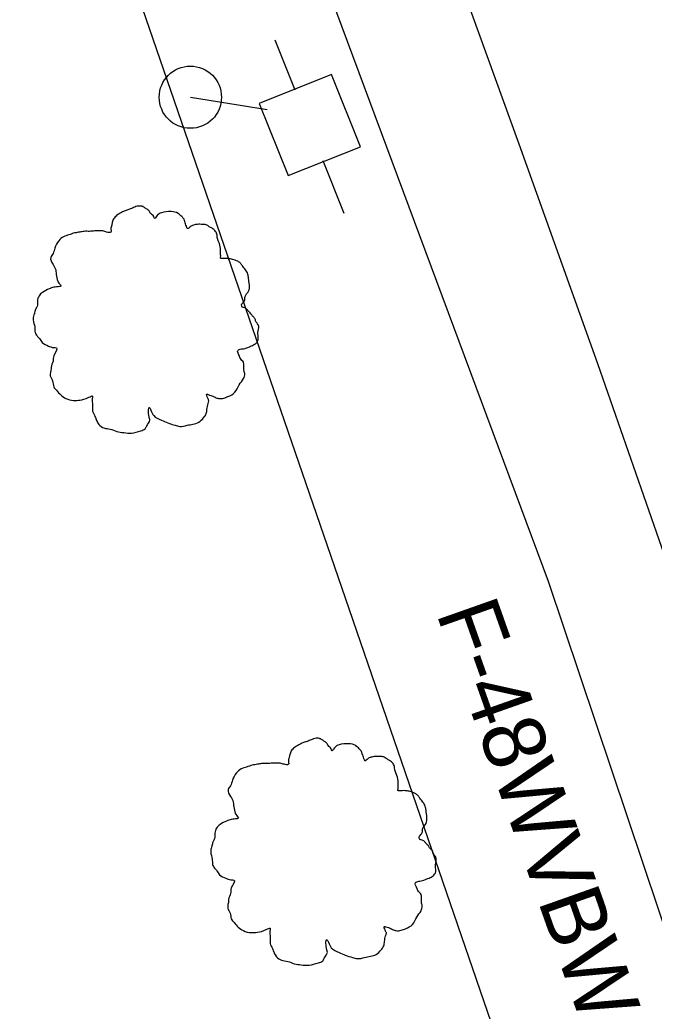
# Model space of a CAD drawing. Extents: x 2004847 to 2009016, y 1134161 to 1140101.
# Drawn here: x 2005383.6 to 2005424.3, y 1139014.6 to 1139078.3 of the extents above; entities that cross this region are included whole.
import ezdxf

# ---------------------------------------------------------------- set-up
doc = ezdxf.new("R2010")
doc.units = 0
for name, color, linetype in [('RD_EX_Fence_Other', 7, 'Continuous'), ('RD_EX_H2O', 7, 'Continuous'), ('RD_EX_Road', 7, 'Continuous'), ('RD_EX_UT', 7, 'Continuous'), ('RD_EX_VEG', 7, 'Continuous'), ('RD_Sketch3', 7, 'Continuous')]:
    doc.layers.add(name, color=color, linetype=linetype)

msp = doc.modelspace()

# ---------------------------------------------------------------- linework, layer by layer
at = {"layer": 'RD_EX_Fence_Other'}
msp.add_lwpolyline([(2005745.196, 1138077.702), (2005734.871, 1138106.228), (2005707.504, 1138183.279), (2005676.139, 1138273.059), (2005651.835, 1138341.758), (2005621.989, 1138424.972), (2005599.093, 1138488.219), (2005571.206, 1138570.22), (2005540.215, 1138656.024), (2005513.7, 1138731.214), (2005485.608, 1138810.484), (2005460.949, 1138877.537), (2005433.241, 1138957.412), (2005403.809, 1139043.224), (2005384.611, 1139099.043), (2005341.775, 1139216.012), (2005309.562, 1139306.929), (2005274.937, 1139406.133)], dxfattribs=at)
at = {"layer": 'RD_EX_H2O'}
msp.add_lwpolyline([(2005471.871, 1138887.945), (2005471.871, 1138887.945), (2005442.962, 1138966.495), (2005417.558, 1139042.223), (2005389.586, 1139117.406), (2005362.32, 1139191.545), (2005330.803, 1139259.793), (2005304.78, 1139341.828)], dxfattribs=at)
at = {"layer": 'RD_EX_Road'}
msp.add_lwpolyline([(2005335.767, 1139296.554), (2005340.823, 1139282.434), (2005345.843, 1139268.3), (2005350.89, 1139254.176), (2005355.796, 1139240.002), (2005360.862, 1139225.885), (2005365.791, 1139211.783), (2005370.883, 1139197.68), (2005375.796, 1139183.516), (2005380.897, 1139169.417), (2005385.734, 1139155.226), (2005390.637, 1139141.059), (2005395.446, 1139126.858), (2005400.445, 1139112.697), (2005405.292, 1139098.51), (2005410.544, 1139084.465), (2005415.646, 1139070.367), (2005420.7, 1139056.252), (2005425.641, 1139042.098), (2005430.526, 1139027.924), (2005435.34, 1139013.754), (2005440.253, 1138999.592), (2005445.203, 1138985.442), (2005450.39, 1138971.373)], dxfattribs=at)
at = {"layer": 'RD_EX_UT'}
for p, q in [((2005399.958, 1139077.064), (2005401.244, 1139073.842)), ((2005403.609, 1139074.827), (2005398.966, 1139072.974)), ((2005405.463, 1139070.184), (2005403.609, 1139074.827)), ((2005394.535, 1139073.368), (2005399.472, 1139072.575)), ((2005398.966, 1139072.974), (2005400.819, 1139068.33)), ((2005400.819, 1139068.33), (2005405.463, 1139070.184)), ((2005403.056, 1139069.3), (2005404.406, 1139065.919))]:
    msp.add_line(p, q, dxfattribs=at)
msp.add_circle((2005394.535, 1139073.368), 1.999, dxfattribs=at)
at = {"layer": 'RD_EX_VEG'}
for points in [[(2005391.505, 1139066.343), (2005391.205, 1139066.368), (2005390.88, 1139066.268), (2005390.631, 1139066.168), (2005390.406, 1139066.093), (2005390.181, 1139065.993), (2005389.881, 1139065.818), (2005389.656, 1139065.618), (2005389.531, 1139065.368), (2005389.481, 1139065.143), (2005389.431, 1139064.868), (2005389.431, 1139064.693), (2005389.306, 1139064.668), (2005389.156, 1139064.693), (2005388.906, 1139064.768), (2005388.656, 1139064.768), (2005388.406, 1139064.768), (2005388.057, 1139064.743), (2005387.707, 1139064.743), (2005387.432, 1139064.693), (2005387.107, 1139064.643), (2005386.732, 1139064.518), (2005386.382, 1139064.393), (2005386.083, 1139064.143), (2005385.833, 1139063.669), (2005385.708, 1139063.319), (2005385.558, 1139063.069), (2005385.708, 1139062.619), (2005385.883, 1139062.269), (2005385.908, 1139062.069), (2005385.983, 1139061.645), (2005386.083, 1139061.42), (2005386.207, 1139061.22), (2005386.133, 1139061.195), (2005385.758, 1139061.145), (2005385.458, 1139061.045), (2005385.033, 1139060.82), (2005384.808, 1139060.595), (2005384.708, 1139060.27), (2005384.683, 1139059.92), (2005384.583, 1139059.72), (2005384.508, 1139059.446), (2005384.483, 1139059.371), (2005384.433, 1139059.046), (2005384.533, 1139058.596), (2005384.558, 1139058.246), (2005384.683, 1139058.021), (2005384.833, 1139057.846), (2005385.008, 1139057.596), (2005385.408, 1139057.371), (2005385.733, 1139057.271), (2005385.933, 1139057.247), (2005385.758, 1139056.747), (2005385.708, 1139056.397), (2005385.583, 1139055.997), (2005385.583, 1139055.922), (2005385.533, 1139055.447), (2005385.683, 1139055.122), (2005385.758, 1139054.748), (2005385.933, 1139054.523), (2005386.207, 1139054.223), (2005386.532, 1139053.998), (2005387.032, 1139053.873), (2005387.432, 1139053.898), (2005388.007, 1139054.073), (2005388.257, 1139054.148), (2005388.232, 1139053.973), (2005388.257, 1139053.598), (2005388.257, 1139053.173), (2005388.406, 1139052.848), (2005388.506, 1139052.574), (2005388.656, 1139052.324), (2005388.981, 1139052.099), (2005389.381, 1139052.024), (2005389.806, 1139051.874), (2005390.256, 1139051.799), (2005390.755, 1139051.774), (2005391.355, 1139051.924), (2005391.63, 1139052.049), (2005391.73, 1139052.224), (2005391.93, 1139052.599), (2005391.88, 1139052.823), (2005391.905, 1139053.423), (2005392.005, 1139053.248), (2005392.18, 1139052.898), (2005392.68, 1139052.599), (2005393.079, 1139052.424), (2005393.554, 1139052.274), (2005393.854, 1139052.199), (2005394.329, 1139052.274), (2005394.704, 1139052.349), (2005395.079, 1139052.474), (2005395.378, 1139052.748), (2005395.553, 1139053.023), (2005395.603, 1139053.298), (2005395.678, 1139053.673), (2005395.728, 1139053.848)], [(2005391.505, 1139066.343), (2005391.205, 1139066.368), (2005390.88, 1139066.268), (2005390.631, 1139066.168), (2005390.406, 1139066.093), (2005390.181, 1139065.993), (2005389.881, 1139065.818), (2005389.656, 1139065.618), (2005389.531, 1139065.368), (2005389.481, 1139065.143), (2005389.431, 1139064.868), (2005389.431, 1139064.693), (2005389.306, 1139064.668), (2005389.156, 1139064.693), (2005388.906, 1139064.768), (2005388.656, 1139064.768), (2005388.406, 1139064.768), (2005388.057, 1139064.743), (2005387.707, 1139064.743), (2005387.432, 1139064.693), (2005387.107, 1139064.643), (2005386.732, 1139064.518), (2005386.382, 1139064.393), (2005386.083, 1139064.143), (2005385.833, 1139063.669), (2005385.708, 1139063.319), (2005385.558, 1139063.069), (2005385.708, 1139062.619), (2005385.883, 1139062.269), (2005385.908, 1139062.069), (2005385.983, 1139061.645), (2005386.083, 1139061.42), (2005386.207, 1139061.22), (2005386.133, 1139061.195), (2005385.758, 1139061.145), (2005385.458, 1139061.045), (2005385.033, 1139060.82), (2005384.808, 1139060.595), (2005384.708, 1139060.27), (2005384.683, 1139059.92), (2005384.583, 1139059.72), (2005384.508, 1139059.446), (2005384.483, 1139059.371), (2005384.433, 1139059.046), (2005384.533, 1139058.596), (2005384.558, 1139058.246), (2005384.683, 1139058.021), (2005384.833, 1139057.846), (2005385.008, 1139057.596), (2005385.408, 1139057.371), (2005385.733, 1139057.271), (2005385.933, 1139057.247), (2005385.758, 1139056.747), (2005385.708, 1139056.397), (2005385.583, 1139055.997), (2005385.583, 1139055.922), (2005385.533, 1139055.447), (2005385.683, 1139055.122), (2005385.758, 1139054.748), (2005385.933, 1139054.523), (2005386.207, 1139054.223), (2005386.532, 1139053.998), (2005387.032, 1139053.873), (2005387.432, 1139053.898), (2005388.007, 1139054.073), (2005388.257, 1139054.148), (2005388.232, 1139053.973), (2005388.257, 1139053.598), (2005388.257, 1139053.173), (2005388.406, 1139052.848), (2005388.506, 1139052.574), (2005388.656, 1139052.324), (2005388.981, 1139052.099), (2005389.381, 1139052.024), (2005389.806, 1139051.874), (2005390.256, 1139051.799), (2005390.755, 1139051.774), (2005391.355, 1139051.924), (2005391.63, 1139052.049), (2005391.73, 1139052.224), (2005391.93, 1139052.599), (2005391.88, 1139052.823), (2005391.905, 1139053.423), (2005392.005, 1139053.248), (2005392.18, 1139052.898), (2005392.68, 1139052.599), (2005393.079, 1139052.424), (2005393.554, 1139052.274), (2005393.854, 1139052.199), (2005394.329, 1139052.274), (2005394.704, 1139052.349), (2005395.079, 1139052.474), (2005395.378, 1139052.748), (2005395.553, 1139053.023), (2005395.603, 1139053.298), (2005395.678, 1139053.673), (2005395.728, 1139053.848)], [(2005395.728, 1139053.848), (2005395.653, 1139054.023), (2005395.603, 1139054.273), (2005395.678, 1139054.248), (2005395.853, 1139054.198), (2005396.128, 1139054.073), (2005396.353, 1139053.998), (2005396.678, 1139054.023), (2005396.953, 1139054.123), (2005397.403, 1139054.398), (2005397.677, 1139054.873), (2005397.952, 1139055.272), (2005398.027, 1139055.597), (2005397.977, 1139055.822), (2005397.952, 1139056.322), (2005397.752, 1139056.572), (2005397.702, 1139056.697), (2005397.602, 1139057.097), (2005397.677, 1139057.147), (2005397.952, 1139057.197), (2005398.327, 1139057.321), (2005398.602, 1139057.446), (2005398.827, 1139057.621), (2005398.902, 1139057.846), (2005398.877, 1139058.246), (2005398.927, 1139058.646), (2005398.852, 1139058.796), (2005398.752, 1139058.946), (2005398.677, 1139059.146), (2005398.527, 1139059.296), (2005398.427, 1139059.446), (2005398.327, 1139059.545), (2005398.202, 1139059.695), (2005398.027, 1139059.82), (2005397.877, 1139059.87), (2005397.827, 1139060.02), (2005397.977, 1139060.22), (2005398.027, 1139060.32), (2005398.052, 1139060.545), (2005398.277, 1139060.895), (2005398.327, 1139061.295), (2005398.277, 1139061.72), (2005398.227, 1139061.994), (2005398.077, 1139062.269), (2005397.877, 1139062.519), (2005397.752, 1139062.694), (2005397.577, 1139062.819), (2005397.253, 1139062.944), (2005397.003, 1139062.994), (2005396.653, 1139062.994), (2005396.453, 1139063.044), (2005396.478, 1139063.094), (2005396.478, 1139063.244), (2005396.478, 1139063.519), (2005396.403, 1139063.969), (2005396.253, 1139064.468), (2005396.253, 1139064.493), (2005396.153, 1139064.743), (2005395.928, 1139064.943), (2005395.753, 1139065.043), (2005395.553, 1139065.168), (2005395.303, 1139065.193), (2005395.004, 1139065.193), (2005394.729, 1139065.143), (2005394.529, 1139065.043), (2005394.354, 1139064.918), (2005394.279, 1139065.068), (2005394.179, 1139065.368), (2005394.129, 1139065.518), (2005393.979, 1139065.693), (2005393.754, 1139065.893), (2005393.304, 1139066.018), (2005392.68, 1139065.943), (2005392.38, 1139065.743), (2005392.23, 1139065.568), (2005392.18, 1139065.693), (2005391.98, 1139065.893), (2005391.88, 1139066.068), (2005391.705, 1139066.193), (2005391.555, 1139066.293), (2005391.455, 1139066.343)], [(2005395.728, 1139053.848), (2005395.653, 1139054.023), (2005395.603, 1139054.273), (2005395.678, 1139054.248), (2005395.853, 1139054.198), (2005396.128, 1139054.073), (2005396.353, 1139053.998), (2005396.678, 1139054.023), (2005396.953, 1139054.123), (2005397.403, 1139054.398), (2005397.677, 1139054.873), (2005397.952, 1139055.272), (2005398.027, 1139055.597), (2005397.977, 1139055.822), (2005397.952, 1139056.322), (2005397.752, 1139056.572), (2005397.702, 1139056.697), (2005397.602, 1139057.097), (2005397.677, 1139057.147), (2005397.952, 1139057.197), (2005398.327, 1139057.321), (2005398.602, 1139057.446), (2005398.827, 1139057.621), (2005398.902, 1139057.846), (2005398.877, 1139058.246), (2005398.927, 1139058.646), (2005398.852, 1139058.796), (2005398.752, 1139058.946), (2005398.677, 1139059.146), (2005398.527, 1139059.296), (2005398.427, 1139059.446), (2005398.327, 1139059.545), (2005398.202, 1139059.695), (2005398.027, 1139059.82), (2005397.877, 1139059.87), (2005397.827, 1139060.02), (2005397.977, 1139060.22), (2005398.027, 1139060.32), (2005398.052, 1139060.545), (2005398.277, 1139060.895), (2005398.327, 1139061.295), (2005398.277, 1139061.72), (2005398.227, 1139061.994), (2005398.077, 1139062.269), (2005397.877, 1139062.519), (2005397.752, 1139062.694), (2005397.577, 1139062.819), (2005397.253, 1139062.944), (2005397.003, 1139062.994), (2005396.653, 1139062.994), (2005396.453, 1139063.044), (2005396.478, 1139063.094), (2005396.478, 1139063.244), (2005396.478, 1139063.519), (2005396.403, 1139063.969), (2005396.253, 1139064.468), (2005396.253, 1139064.493), (2005396.153, 1139064.743), (2005395.928, 1139064.943), (2005395.753, 1139065.043), (2005395.553, 1139065.168), (2005395.303, 1139065.193), (2005395.004, 1139065.193), (2005394.729, 1139065.143), (2005394.529, 1139065.043), (2005394.354, 1139064.918), (2005394.279, 1139065.068), (2005394.179, 1139065.368), (2005394.129, 1139065.518), (2005393.979, 1139065.693), (2005393.754, 1139065.893), (2005393.304, 1139066.018), (2005392.68, 1139065.943), (2005392.38, 1139065.743), (2005392.23, 1139065.568), (2005392.18, 1139065.693), (2005391.98, 1139065.893), (2005391.88, 1139066.068), (2005391.705, 1139066.193), (2005391.555, 1139066.293), (2005391.455, 1139066.343)], [(2005402.915, 1139032.121), (2005402.615, 1139032.146), (2005402.29, 1139032.046), (2005402.041, 1139031.947), (2005401.816, 1139031.872), (2005401.591, 1139031.772), (2005401.291, 1139031.597), (2005401.066, 1139031.397), (2005400.941, 1139031.147), (2005400.891, 1139030.922), (2005400.841, 1139030.647), (2005400.841, 1139030.472), (2005400.716, 1139030.447), (2005400.566, 1139030.472), (2005400.316, 1139030.547), (2005400.066, 1139030.547), (2005399.816, 1139030.547), (2005399.467, 1139030.522), (2005399.117, 1139030.522), (2005398.842, 1139030.472), (2005398.517, 1139030.422), (2005398.142, 1139030.297), (2005397.792, 1139030.172), (2005397.493, 1139029.922), (2005397.243, 1139029.448), (2005397.118, 1139029.098), (2005396.968, 1139028.848), (2005397.118, 1139028.398), (2005397.293, 1139028.048), (2005397.318, 1139027.848), (2005397.393, 1139027.424), (2005397.493, 1139027.199), (2005397.617, 1139026.999), (2005397.543, 1139026.974), (2005397.168, 1139026.924), (2005396.868, 1139026.824), (2005396.443, 1139026.599), (2005396.218, 1139026.374), (2005396.118, 1139026.049), (2005396.093, 1139025.699), (2005395.993, 1139025.499), (2005395.918, 1139025.224), (2005395.893, 1139025.149), (2005395.843, 1139024.825), (2005395.943, 1139024.375), (2005395.968, 1139024.025), (2005396.093, 1139023.8), (2005396.243, 1139023.625), (2005396.418, 1139023.375), (2005396.818, 1139023.15), (2005397.143, 1139023.05), (2005397.343, 1139023.025), (2005397.168, 1139022.526), (2005397.118, 1139022.176), (2005396.993, 1139021.776), (2005396.993, 1139021.701), (2005396.943, 1139021.226), (2005397.093, 1139020.901), (2005397.168, 1139020.527), (2005397.343, 1139020.302), (2005397.617, 1139020.002), (2005397.942, 1139019.777), (2005398.442, 1139019.652), (2005398.842, 1139019.677), (2005399.417, 1139019.852), (2005399.667, 1139019.927), (2005399.642, 1139019.752), (2005399.667, 1139019.377), (2005399.667, 1139018.952), (2005399.816, 1139018.627), (2005399.916, 1139018.352), (2005400.066, 1139018.103), (2005400.391, 1139017.878), (2005400.791, 1139017.803), (2005401.216, 1139017.653), (2005401.666, 1139017.578), (2005402.165, 1139017.553), (2005402.765, 1139017.703), (2005403.04, 1139017.828), (2005403.14, 1139018.003), (2005403.34, 1139018.377), (2005403.29, 1139018.602), (2005403.315, 1139019.202), (2005403.415, 1139019.027), (2005403.59, 1139018.677), (2005404.09, 1139018.377), (2005404.489, 1139018.203), (2005404.964, 1139018.053), (2005405.264, 1139017.978), (2005405.739, 1139018.053), (2005406.114, 1139018.128), (2005406.489, 1139018.253), (2005406.788, 1139018.527), (2005406.963, 1139018.802), (2005407.013, 1139019.077), (2005407.088, 1139019.452), (2005407.138, 1139019.627)], [(2005402.915, 1139032.121), (2005402.615, 1139032.146), (2005402.29, 1139032.046), (2005402.041, 1139031.947), (2005401.816, 1139031.872), (2005401.591, 1139031.772), (2005401.291, 1139031.597), (2005401.066, 1139031.397), (2005400.941, 1139031.147), (2005400.891, 1139030.922), (2005400.841, 1139030.647), (2005400.841, 1139030.472), (2005400.716, 1139030.447), (2005400.566, 1139030.472), (2005400.316, 1139030.547), (2005400.066, 1139030.547), (2005399.816, 1139030.547), (2005399.467, 1139030.522), (2005399.117, 1139030.522), (2005398.842, 1139030.472), (2005398.517, 1139030.422), (2005398.142, 1139030.297), (2005397.792, 1139030.172), (2005397.493, 1139029.922), (2005397.243, 1139029.448), (2005397.118, 1139029.098), (2005396.968, 1139028.848), (2005397.118, 1139028.398), (2005397.293, 1139028.048), (2005397.318, 1139027.848), (2005397.393, 1139027.424), (2005397.493, 1139027.199), (2005397.617, 1139026.999), (2005397.543, 1139026.974), (2005397.168, 1139026.924), (2005396.868, 1139026.824), (2005396.443, 1139026.599), (2005396.218, 1139026.374), (2005396.118, 1139026.049), (2005396.093, 1139025.699), (2005395.993, 1139025.499), (2005395.918, 1139025.224), (2005395.893, 1139025.149), (2005395.843, 1139024.825), (2005395.943, 1139024.375), (2005395.968, 1139024.025), (2005396.093, 1139023.8), (2005396.243, 1139023.625), (2005396.418, 1139023.375), (2005396.818, 1139023.15), (2005397.143, 1139023.05), (2005397.343, 1139023.025), (2005397.168, 1139022.526), (2005397.118, 1139022.176), (2005396.993, 1139021.776), (2005396.993, 1139021.701), (2005396.943, 1139021.226), (2005397.093, 1139020.901), (2005397.168, 1139020.527), (2005397.343, 1139020.302), (2005397.617, 1139020.002), (2005397.942, 1139019.777), (2005398.442, 1139019.652), (2005398.842, 1139019.677), (2005399.417, 1139019.852), (2005399.667, 1139019.927), (2005399.642, 1139019.752), (2005399.667, 1139019.377), (2005399.667, 1139018.952), (2005399.816, 1139018.627), (2005399.916, 1139018.352), (2005400.066, 1139018.103), (2005400.391, 1139017.878), (2005400.791, 1139017.803), (2005401.216, 1139017.653), (2005401.666, 1139017.578), (2005402.165, 1139017.553), (2005402.765, 1139017.703), (2005403.04, 1139017.828), (2005403.14, 1139018.003), (2005403.34, 1139018.377), (2005403.29, 1139018.602), (2005403.315, 1139019.202), (2005403.415, 1139019.027), (2005403.59, 1139018.677), (2005404.09, 1139018.377), (2005404.489, 1139018.203), (2005404.964, 1139018.053), (2005405.264, 1139017.978), (2005405.739, 1139018.053), (2005406.114, 1139018.128), (2005406.489, 1139018.253), (2005406.788, 1139018.527), (2005406.963, 1139018.802), (2005407.013, 1139019.077), (2005407.088, 1139019.452), (2005407.138, 1139019.627)], [(2005407.138, 1139019.627), (2005407.063, 1139019.802), (2005407.013, 1139020.052), (2005407.088, 1139020.027), (2005407.263, 1139019.977), (2005407.538, 1139019.852), (2005407.763, 1139019.777), (2005408.088, 1139019.802), (2005408.363, 1139019.902), (2005408.813, 1139020.177), (2005409.087, 1139020.651), (2005409.362, 1139021.051), (2005409.437, 1139021.376), (2005409.387, 1139021.601), (2005409.362, 1139022.101), (2005409.162, 1139022.351), (2005409.112, 1139022.476), (2005409.012, 1139022.875), (2005409.087, 1139022.925), (2005409.362, 1139022.975), (2005409.737, 1139023.1), (2005410.012, 1139023.225), (2005410.237, 1139023.4), (2005410.312, 1139023.625), (2005410.287, 1139024.025), (2005410.337, 1139024.425), (2005410.262, 1139024.575), (2005410.162, 1139024.725), (2005410.087, 1139024.925), (2005409.937, 1139025.074), (2005409.837, 1139025.224), (2005409.737, 1139025.324), (2005409.612, 1139025.474), (2005409.437, 1139025.599), (2005409.287, 1139025.649), (2005409.237, 1139025.799), (2005409.387, 1139025.999), (2005409.437, 1139026.099), (2005409.462, 1139026.324), (2005409.687, 1139026.674), (2005409.737, 1139027.074), (2005409.687, 1139027.498), (2005409.637, 1139027.773), (2005409.487, 1139028.048), (2005409.287, 1139028.298), (2005409.162, 1139028.473), (2005408.987, 1139028.598), (2005408.663, 1139028.723), (2005408.413, 1139028.773), (2005408.063, 1139028.773), (2005407.863, 1139028.823), (2005407.888, 1139028.873), (2005407.888, 1139029.023), (2005407.888, 1139029.298), (2005407.813, 1139029.747), (2005407.663, 1139030.247), (2005407.663, 1139030.272), (2005407.563, 1139030.522), (2005407.338, 1139030.722), (2005407.163, 1139030.822), (2005406.963, 1139030.947), (2005406.713, 1139030.972), (2005406.414, 1139030.972), (2005406.139, 1139030.922), (2005405.939, 1139030.822), (2005405.764, 1139030.697), (2005405.689, 1139030.847), (2005405.589, 1139031.147), (2005405.539, 1139031.297), (2005405.389, 1139031.472), (2005405.164, 1139031.672), (2005404.714, 1139031.797), (2005404.09, 1139031.722), (2005403.79, 1139031.522), (2005403.64, 1139031.347), (2005403.59, 1139031.472), (2005403.39, 1139031.672), (2005403.29, 1139031.847), (2005403.115, 1139031.972), (2005402.965, 1139032.071), (2005402.865, 1139032.121)], [(2005407.138, 1139019.627), (2005407.063, 1139019.802), (2005407.013, 1139020.052), (2005407.088, 1139020.027), (2005407.263, 1139019.977), (2005407.538, 1139019.852), (2005407.763, 1139019.777), (2005408.088, 1139019.802), (2005408.363, 1139019.902), (2005408.813, 1139020.177), (2005409.087, 1139020.651), (2005409.362, 1139021.051), (2005409.437, 1139021.376), (2005409.387, 1139021.601), (2005409.362, 1139022.101), (2005409.162, 1139022.351), (2005409.112, 1139022.476), (2005409.012, 1139022.875), (2005409.087, 1139022.925), (2005409.362, 1139022.975), (2005409.737, 1139023.1), (2005410.012, 1139023.225), (2005410.237, 1139023.4), (2005410.312, 1139023.625), (2005410.287, 1139024.025), (2005410.337, 1139024.425), (2005410.262, 1139024.575), (2005410.162, 1139024.725), (2005410.087, 1139024.925), (2005409.937, 1139025.074), (2005409.837, 1139025.224), (2005409.737, 1139025.324), (2005409.612, 1139025.474), (2005409.437, 1139025.599), (2005409.287, 1139025.649), (2005409.237, 1139025.799), (2005409.387, 1139025.999), (2005409.437, 1139026.099), (2005409.462, 1139026.324), (2005409.687, 1139026.674), (2005409.737, 1139027.074), (2005409.687, 1139027.498), (2005409.637, 1139027.773), (2005409.487, 1139028.048), (2005409.287, 1139028.298), (2005409.162, 1139028.473), (2005408.987, 1139028.598), (2005408.663, 1139028.723), (2005408.413, 1139028.773), (2005408.063, 1139028.773), (2005407.863, 1139028.823), (2005407.888, 1139028.873), (2005407.888, 1139029.023), (2005407.888, 1139029.298), (2005407.813, 1139029.747), (2005407.663, 1139030.247), (2005407.663, 1139030.272), (2005407.563, 1139030.522), (2005407.338, 1139030.722), (2005407.163, 1139030.822), (2005406.963, 1139030.947), (2005406.713, 1139030.972), (2005406.414, 1139030.972), (2005406.139, 1139030.922), (2005405.939, 1139030.822), (2005405.764, 1139030.697), (2005405.689, 1139030.847), (2005405.589, 1139031.147), (2005405.539, 1139031.297), (2005405.389, 1139031.472), (2005405.164, 1139031.672), (2005404.714, 1139031.797), (2005404.09, 1139031.722), (2005403.79, 1139031.522), (2005403.64, 1139031.347), (2005403.59, 1139031.472), (2005403.39, 1139031.672), (2005403.29, 1139031.847), (2005403.115, 1139031.972), (2005402.965, 1139032.071), (2005402.865, 1139032.121)]]:
    msp.add_spline(points, degree=3, dxfattribs=at)

# ---------------------------------------------------------------- texts
at = {"layer": 'RD_Sketch3'}
msp.add_text('F-48WVBW', height=4, rotation=289.44941, dxfattribs=at).set_placement((2005410.316, 1139040.216))

doc.saveas('drawing.dxf')
